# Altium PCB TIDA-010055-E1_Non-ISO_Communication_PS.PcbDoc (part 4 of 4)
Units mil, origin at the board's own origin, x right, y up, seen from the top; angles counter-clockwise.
Board outline 3937.01 x 3346.46 mil, 2 copper layers (Top Layer, Bottom Layer), stack 62 mil thick; 328 components, 142 nets, 761 pads, 214 vias.
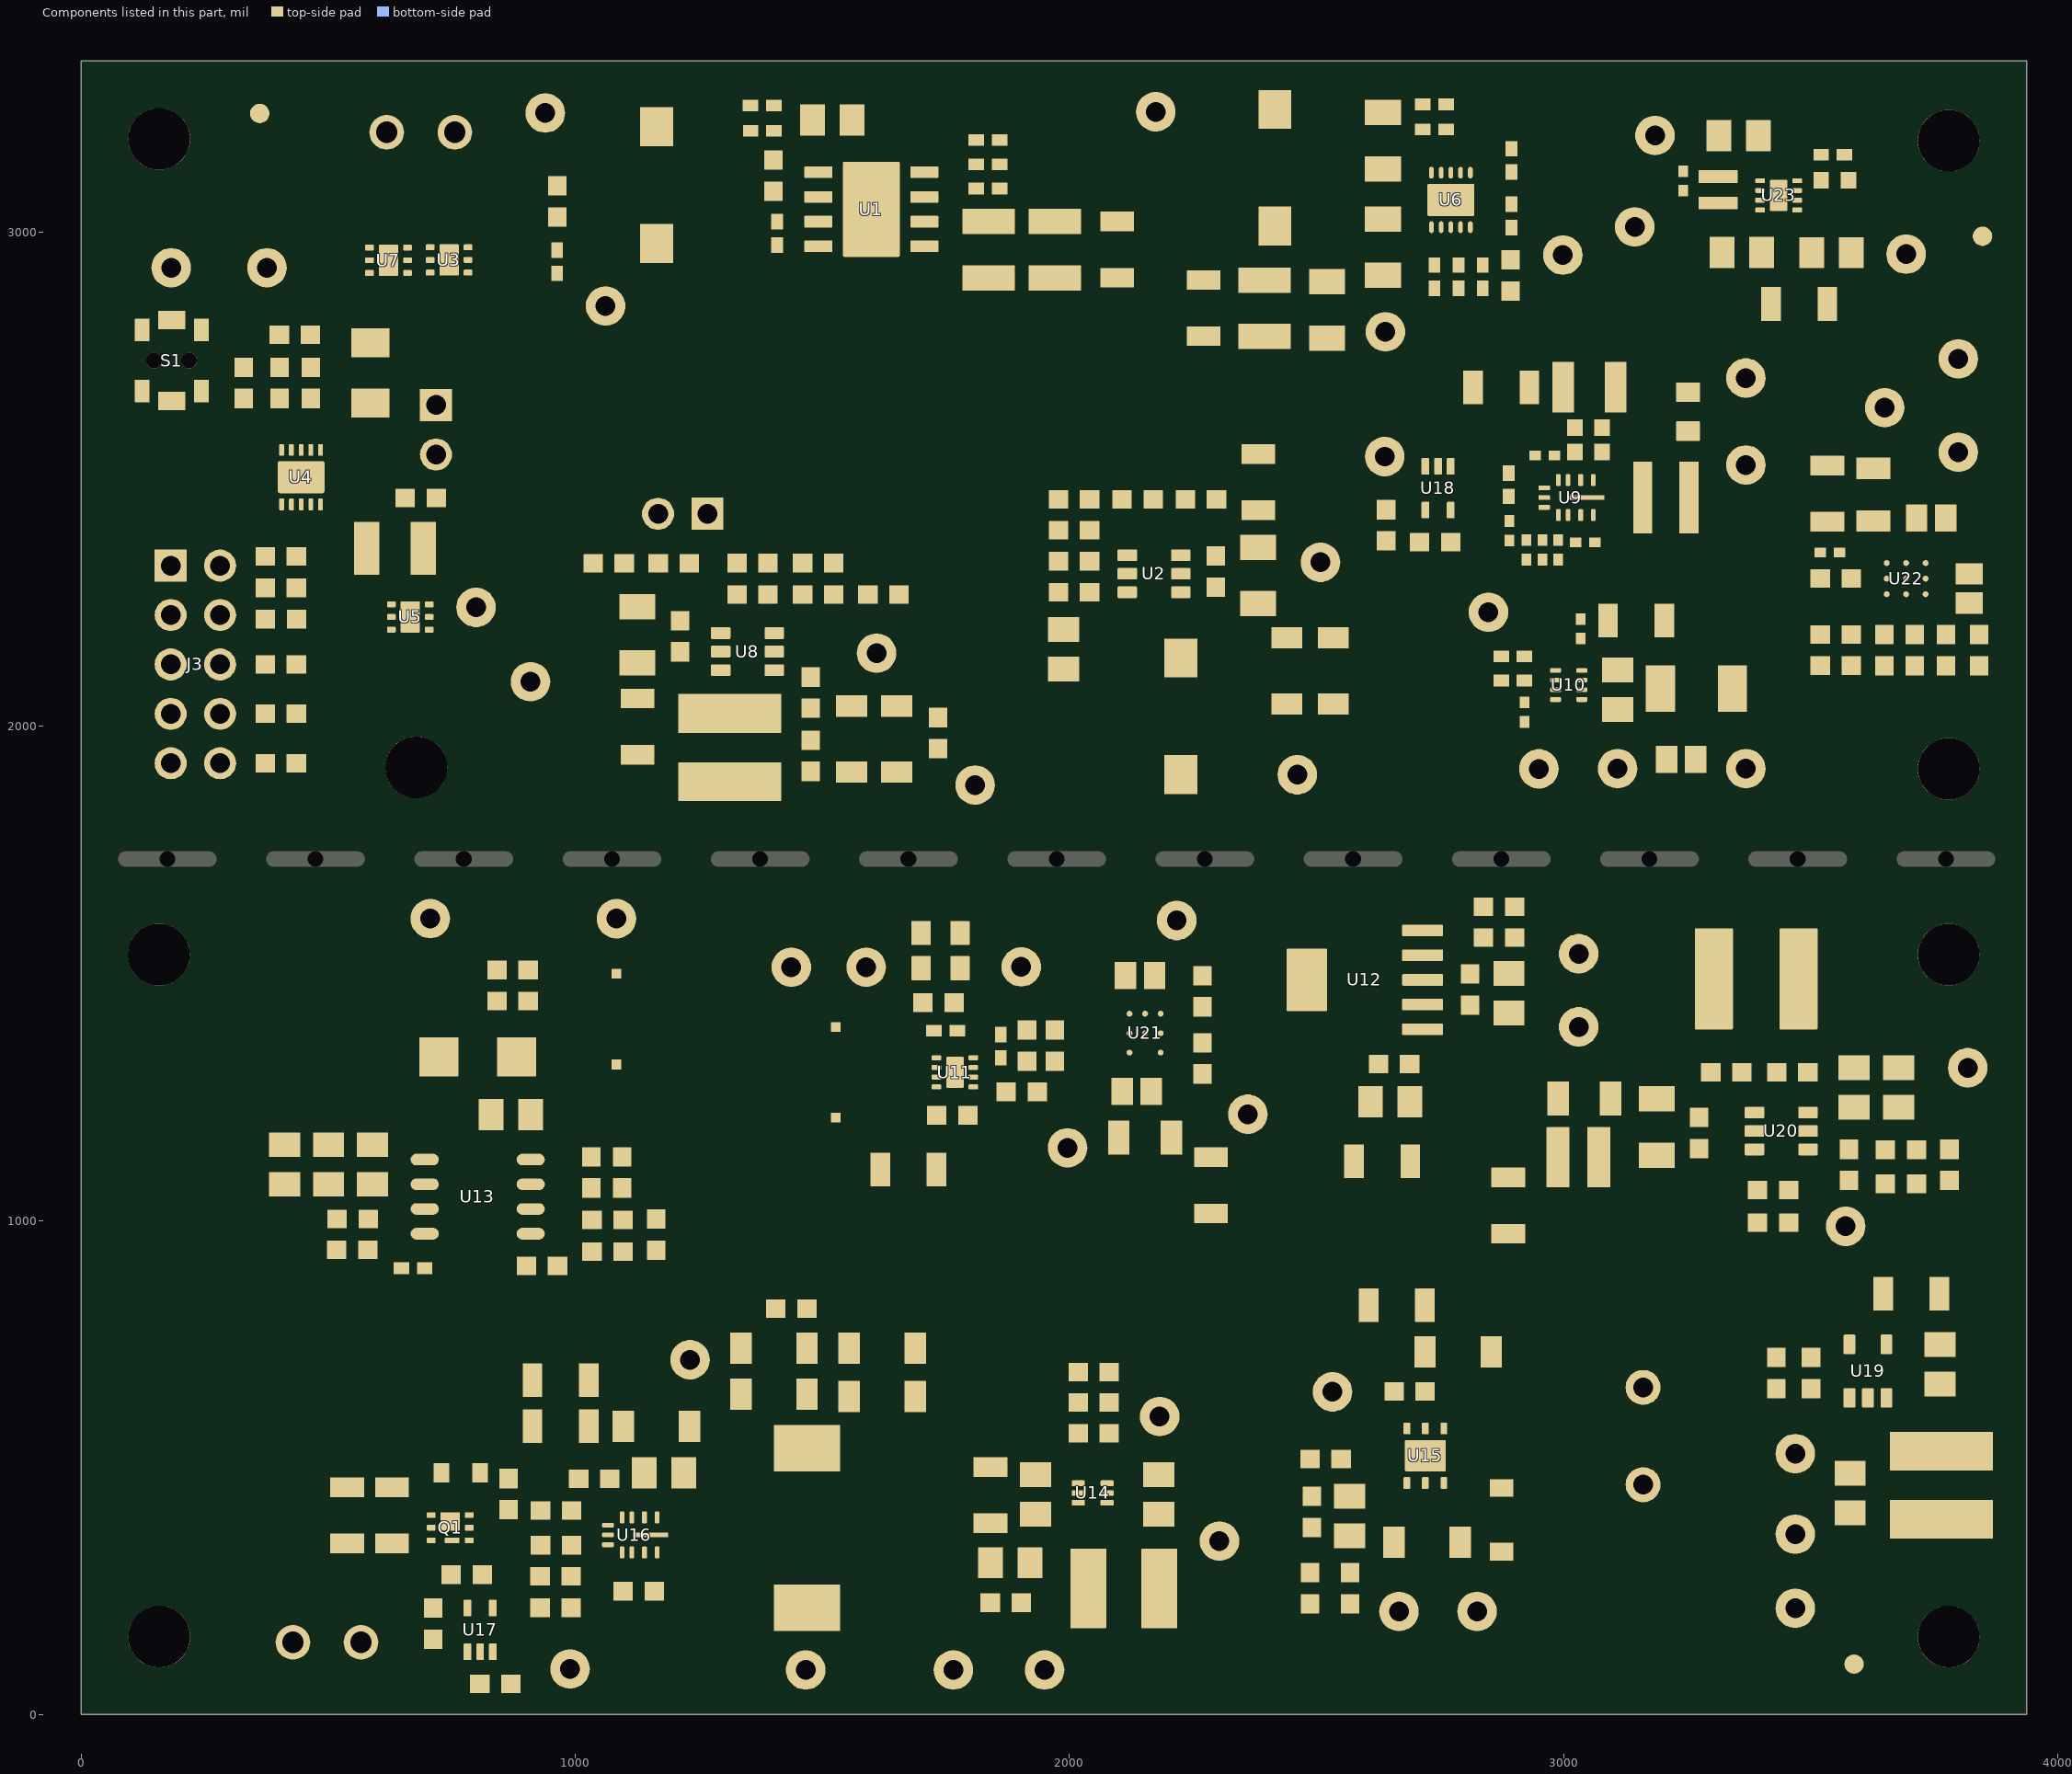
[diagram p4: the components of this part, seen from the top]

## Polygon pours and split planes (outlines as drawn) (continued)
GND_P on Top Layer "net" (solid, remove dead copper, pour order 20): 629.78,2751.18 629.78,2807.35 614.78,2822.35 588.78,2848.35 588.78,2900.35 588.78,3094.18 655.78,3161.18 655.78,3232.62 645,3243.4 487,3243.4 480.78,3237.18 480.78,2860.35 505.78,2835.35 533,2808.13 533,2749.4 539.05,2743.35 554.78,2743.35 621.95,2743.35
NetU3_1 on Top Layer "gn" (solid, remove dead copper, pour order 62): 602,2941.4 602,2978.4 614,2990.4 751,2990.4 764,2977.4 764,2915.4 755,2906.4 612,2906.4 602,2916.4
GND_P on Top Layer "gn" (solid, remove dead copper, pour order 64): 649,2269.4 657.62,2278.02 657.62,2278.19 657.62,2413.19 661.78,2417.35 839.05,2417.35 857,2399.4 857,2181.4 850,2174.4 656,2174.4 649,2181.4
NetC30_2 on Top Layer "gn" (solid, remove dead copper, pour order 66): 3040,2572.1 3040,2741 3030,2751 2912,2751 2902,2741 2902,2585 2909.9,2577.1 2996.96,2577.1 3002.96,2571.1 3002.96,2540.68 3009,2534.63 3037.54,2534.63 3040,2537.1
GND_P on Top Layer "gn" (solid, remove dead copper, pour order 72): 3054,2506.1 3054,2530.1 3060,2536.1 3060,2733.45 3073.65,2747.1 3415,2747.1 3425,2737.1 3425,2658.1 3417,2650.1 3276,2650.1 3193,2650.1 3185,2642.1 3185,2578.1 3179,2572.1 3118,2572.1 3106,2572.1 3101,2567.1 3101,2491.1 3095,2485.1 3057,2485.1 3054,2488.1
NetC33_2 on Top Layer "gn" (solid, remove dead copper, pour order 74): 3187,2544.1 3187,2390.1 3181,2384.1 3131,2384.1 3124,2391.1 3124,2445.1 3116,2453.1 3114,2455.1 3010,2455.1 3006,2459.1 3006,2462.1 3006,2467.88 3009.11,2470.99 3114.24,2470.99 3122.35,2479.1 3122.35,2538.1 3132,2547.74 3183.06,2547.74 3187,2543.81
GND_P on Top Layer "gn" (solid, remove dead copper, pour order 76): 3220.37,1984.83 3159.37,1984.83 3149.37,1994.83 3149.37,2054.83 3142.37,2061.83 3027.37,2061.83 3024.37,2058.83 3024.37,1870.04 3036,1858.4 3218,1858.4 3225,1865.4 3225,1980.2
NetC5_2 on Top Layer "gn" (solid, pour order 92): 1681.13,3003.88 1765.13,3003.88 1777.13,2991.88 2136.13,2991.88 2141.13,2996.88 2141.13,3049.88 2138.13,3052.88 2021.13,3052.88 1681.13,3052.88 1675.13,3046.88 1675.13,3006.88 1678.13,3003.88
NetC8_1 on Top Layer "gn" (solid, pour order 94): 2430,2337.3 2416,2323.3 2276,2323.3 2267,2332.3 2200,2332.3 2195,2337.3 2195,2394.3 2205,2404.3 2333,2404.3 2339,2410.3 2339,2471.3 2345,2477.3 2420,2477.3 2430,2467.3
NetC15_1 on Top Layer "gn" (solid, pour order 104): 2664.68,2942.85 2233.68,2942.85 2228.68,2937.85 2228.68,2878.85 2232.68,2874.85 2233.68,2873.85 2663.68,2873.85 2670.68,2873.85 2681.68,2884.85 2681.68,2935.85 2674.68,2942.85
NetC21_1 on Top Layer "gn" (solid, pour order 110): 1280.73,2166.51 1083.73,2166.51 1073.73,2156.51 1073.73,2038.67 1079.89,2032.51 1157.73,2032.51 1165.73,2040.51 1165.73,2083.72 1172.84,2090.83 1210.29,2090.83 1240.75,2121.3 1254.96,2135.51 1290.73,2135.51 1306.64,2135.51 1315.64,2144.51 1315.64,2159.6 1308.73,2166.51
NetC50_1 on Top Layer "gn" (solid, pour order 116): 944.74,1121.79 944.74,1239.79 966.74,1261.79 1186.2,1261.79 1195.74,1271.33 1195.74,1381.79 1186.74,1390.79 886.74,1390.79 843.74,1390.79 833.74,1380.79 833.74,1295.79 874.74,1254.79 874.74,1199.79 874.74,1113.79 881.74,1106.79 939.74,1106.79 944.74,1111.79
NetC40_1 on Top Layer "gn" (solid, pour order 122): 1753.52,1167.23 1753.52,1066.16 1748.66,1061.31 1698.1,1061.31 1694.15,1065.26 1694.15,1217.86 1709.52,1233.23 1709.52,1270.23 1714.52,1275.23 1736.52,1275.23 1741.52,1270.23 1741.52,1245.23 1753.52,1233.23
NetC35_1 on Top Layer "gn" (solid, pour order 128): 3144.52,2112.99 3144.52,2243.99 3139.52,2248.99 3024.52,2248.99 3020.52,2244.99 3020.52,2206.99 3022.52,2204.99 3063.52,2204.99 3067.52,2200.99 3067.52,2096.99 3077.52,2086.99 3140.52,2086.99 3144.52,2090.99
NetL7_1 on Top Layer "gn" (solid, pour order 134): 1630.18,1184.23 1423.18,1184.23 1413.18,1194.23 1413.18,1261.03 1422.85,1270.7 1601.65,1270.7 1619.18,1288.23 1682.39,1288.23 1688.39,1282.23 1688.39,1242.23 1675.39,1229.23
NetC41_1 on Top Layer "gn" (solid, pour order 138): 1742.18,1325.23 1742.18,1397.44 1719.39,1420.23 1719.39,1615.23 1709.39,1625.23 1513.18,1625.23 1500.18,1612.23 1500.18,1434.23 1486.18,1420.23 1419.18,1420.23 1410.18,1411.23 1410.18,1342.42 1422.85,1329.75 1423.32,1329.28 1685.34,1329.28 1685.34,1328.07 1688.18,1325.23
VO3 on Top Layer "gn" (solid, pour order 140): 3246,1977.4 3282,2013.4 3282,2114.4 3295,2127.4 3431,2127.4 3431,1870.4 3426,1865.4 3419,1858.4 3252,1858.4 3246,1864.4
NetC60_1 on Top Layer "gn" (solid, pour order 142): 2003.54,435.96 1794.54,435.96 1791.54,432.96 1790.54,431.96 1790.54,422.96 1790.54,362.96 1794.54,358.96 1975.49,358.96 2027.32,410.79 2032.54,416.01 2032.54,426.96 2032.54,433.96 2030.54,435.96
NetL9_1 on Top Layer "gn" (solid, pour order 144): 1997.54,179.96 1997.54,350.96 2054.54,407.96 2054.54,431.96 2058.54,435.96 2090.54,435.96 2092.54,433.96 2092.54,156.96 2081.54,145.96 2003.54,145.96 1997.54,151.96
3.3V/2A on Top Layer "gn" (solid, pour order 146): 2139.54,175.96 2139.54,428.96 2146.54,435.96 2348.25,435.96 2364.25,419.96 2364.25,164.66 2345.54,145.96 2145.54,145.96 2139.54,151.96
GND on Top Layer "gn" (solid, pour order 148): 2154.54,458.96 2288.54,458.96 2307.54,477.96 2307.54,650.96 2295.54,662.96 2136.54,662.96 2126.54,652.96 2126.54,597.96 2121.54,592.96 2059.54,592.96 2056.54,589.96 2056.54,466.96 2064.54,458.96
NetC62_1 on Top Layer "gn" (solid, pour order 152): 2698.4,643 2698.4,862 2704.4,868 3009,868 3219.14,657.86 3219.13,646.12 3171.73,598.72 3157.28,598.72 2969,787 2836.4,787 2760.4,787 2755.4,782 2755.4,641 2732.4,618 2732.4,572 2726.4,566 2711.4,566 2705.4,572 2705.4,617 2698.4,624 2698.4,637
GND on Top Layer "gn" (solid, pour order 154): 2679.4,556 2745.4,556 2750.4,561 2750.4,604 2763.4,617 2783.4,637 2783.4,745 2783.4,761 2789.4,767 2880.4,767 2886.4,761 2886.4,577 2841.4,532 2801.4,492 2762.4,492 2732.4,492 2728.4,488 2728.4,166 2723.4,161 2718.4,156 2670.4,156 2626.4,156 2618.4,164 2615.4,167 2615.4,229 2615.4,371 2665.4,421 2704.4,460 2704.4,480 2704.4,487 2699.4,492 2535.4,492 2528.4,499 2528.4,549 2535.4,556
NetD3_1 on Top Layer "gn" (solid, pour order 166): 793,369 701,369 696,374 696,417.94 701.34,423.28 798.72,423.28 801,421 801,377
+5V_P on Top Layer "gn" (solid, pour order 180): 2063,1821.3 2494.3,1821.3 2515,1842 2515,1971 2568,2024 2568,2068 2565,2071 2398,2071 2388,2061 2388,2009 2368,1989 2366.3,1987.3 2053,1987.3 2046,1980.3 2046,1838.3 2063,1821.3
GND_P on Top Layer "gn" (solid, pour order 182): 2204.93,2279.69 2204.93,2222.37 2211,2216.3 2362.7,2216.3 2380,2199 2380,2151 2388,2143 2565,2143 2574,2152 2574,2373 2560,2387 2461,2387 2456,2382 2456,2322 2438,2304 2437.7,2304.3 2275,2304.3 2258,2287.3 2207.3,2287.3 2204,2284
NetC66_1 on Top Layer "gn" (solid, pour order 184): 1109,458 1109,537 1103,543 1003,543 997,549 997,718 1002,723 1126,723 1157,723 1164,716 1168,712 1168,513 1168,450.33 1163.29,445.62 1120.38,445.62 1109,457
24V on Top Layer "gn" (solid, pour order 186): 935,723 785,723 776,714 776,552 782,546 935,546 938,549 938,720
NetL12_1 on Top Layer "vo" (solid, pour order 190): 3881,503 3881,606 3875,612 3715,612 3709,618 3709,659 3702,666 3643,666 3643,497 3652,488 3876,488 3881,493
GND on Top Layer "vo" (solid, pour order 192): 3620,663.47 3604.47,663.47 3600,659 3600,604 3593,597 3472,597 3442,567 3426,551 3426,492 3426,478 3439,465 3443,461 3558,461 3613,461 3620,468
NetC77_1 on Top Layer "vo" (solid, pour order 194): 3605,437 3874,437 3882,429 3882,314.53 3872.47,305 3427,305 3414,318 3414,425 3426,437
NetD2_2 on Top Layer "vo" (solid, pour order 196): 2753.4,410 3213,410 3222,419 3222,487 3207,502 3004.81,502 2984.81,482 2749.57,482 2744.4,476.83 2744.4,419 2753.4,410
NetC76_1 on Top Layer "vo" (solid, pour order 198): 3642,726.47 3804.47,726.47 3810,732 3810,887 3804,893 3739,893 3735,889 3735,796 3722,783 3644,783 3637,776 3637,729.47 3640,726.47
NetC79_1 on Top Layer "vo" (solid, pour order 202): 3413.05,1120.94 3355.94,1120.94 3325,1090 3291,1056 3174,1056 3049,1056 3042,1063 3042,1186 3047,1191 3111,1191 3138,1164 3410,1164 3415,1159 3415,1122.9 3413.05,1120.94
NetC82_1 on Top Layer "vo" (solid, pour order 206): 3722,1277 3554,1277 3547,1284 3547,1357 3540,1364 3438,1364 3429,1373 3429,1602 3440,1613 3613,1613 3642,1584 3642,1415 3677,1380 3884,1380 3901,1363 3901,1141 3882,1122 3758,1122 3753,1127 3753,1267 3743,1277
NetC78_2 on Top Layer "vo" (solid, pour order 208): 3230,1304 3230,1597 3242,1609 3246.02,1613.02 3337.98,1613.02 3350,1601 3350,1378 3327,1355 3327,1275 3318,1266 3261,1266 3230,1297
DC_I on Top Layer "vo" (solid, pour order 210): 474,2407 477.57,2410.57 477.57,2461.72 571.68,2461.72 604.78,2428.62 604.78,2298.1 634.28,2268.59 634.28,2167.28 663.16,2138.4 863.4,2138.4 879,2154 879,2616 991.4,2728.4 2040,2728.4 2058,2746.4 2058,2935.4 2065,2942.4 2147,2942.4 2154,2935.4 2154,2844.4 2171,2827.4 2300.72,2827.4 2311,2817.12 2311,2737 2320,2728 2832,2728 2840,2720 2840,2614 2830.4,2604.4 2688.4,2604.4 2466.4,2604.4 2450,2588 2450,2528 2444,2522 2346,2522 2338,2530 2338,2592.8 2326.4,2604.4 1069.56,2604.4 992,2526.84 992,2041.4 1051,1982.4 1170,1982.4 1172,1980.4 1172,1894.4 1170,1892.4 957.6,1892.4 817.6,2032.4 532,2032.4 514.78,2049.62 514.78,2366.22
NetC91_1 on Top Layer "n" (solid, pour order 238): 3373,2822 3380,2815 3452,2815 3455,2818 3455,2905.42 3468.31,2918.72 3530.72,2918.72 3533,2921 3533,3040.44 3520.37,3053.07 3465.07,3053.07 3461,3049 3461,3032.45 3458,3029.45 3415.94,3029.45 3412,3033.39 3412,3048 3407,3053 3377,3053 3373,3049
VO1 on Top Layer "n" (solid, pour order 240): 3219,2378.45 3219,2621.47 3222.52,2624.99 3463.99,2624.99 3483,2644 3483,2886 3489,2892 3554,2892 3558,2888 3558,2559 3569.61,2547.39 3569.61,2495.61 3562,2488 3446,2488 3438,2480 3438,2184 3425,2171 3182.38,2171 3175,2178.38 3175,2255 3181,2261 3305,2261 3317,2273 3317,2543.34 3312.95,2547.39 3291.29,2547.39 3287.71,2543.81 3287.71,2372.17 3284.52,2368.99 3226.52,2368.99 3218.52,2376.99
NetC93_1 on Top Layer "n" (solid, pour order 242): 3274,3099 3264,3109 3139,3109 3132,3116 3132,3244 3140,3252 3334,3252 3343,3243 3343,3149 3348,3144 3405,3144 3409,3140 3409,3103 3405,3099
GND_P on Top Layer "n" (solid, pour order 244): 3414,3161 3423,3152 3423,3113 3415,3105 3415,3045 3419,3041 3451,3041 3453,3043 3453,3055 3459,3061 3545,3061 3552,3054 3552,2921 3557,2916 3735,2916 3739,2920 3739,3042 3655.33,3125.67 3559.67,3125.67 3555,3121 3555,3082 3551,3078 3495,3078 3483,3090 3458,3090 3455,3093 3455,3121 3474,3140 3474,3244 3466,3252 3368,3252 3362,3246 3362,3166 3367,3161
GND on Bottom Layer "gn" (solid, pour order 174): 341.14,1666.14 57.14,1666.14 36,1645 36,60 60,36 3839.32,36 3937.01,133.69 3937.01,1576.99 3847.86,1666.14
NetL3_1 on Bottom Layer "net" (solid, remove dead copper, pour order 40): 2325.5,3048.62 2577.68,3048.62 2595.86,3030.45 2712.68,3030.45 2720.5,3022.63 2720.5,2972.62 2720.5,2967.26 2712.45,2959.21 2319.91,2959.21 2316.5,2962.62 2316.5,2985.62 2316.5,3039.62
GND_P on Bottom Layer "gn" (solid, remove dead copper, pour order 130): 0,1860 0,3202.4 144.06,3346.46 3798.54,3346.46 3937.01,3207.99 3937.01,1949.01 3772,1784 76,1784
24V on Bottom Layer "gn" (solid, pour order 2): 499,92 499,499 723,723 868,723 879,712 879,560 865,546 787,546 759,518 669,428 669,370 669,90 664,85 506,85
NetC78_2 on Bottom Layer "vo" (solid, pour order 0): 3374,1166 3241,1166 3228,1179 3228,1354 3238,1364 3318,1364 3327,1355 3327,1266.91 3384.03,1209.88 3384.03,1172.03 3378,1166

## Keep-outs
Keep-Out Layer:
  the board outline again, w10
  text ".Layer_Name" at 211.39,-1758.67 h60

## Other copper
Top Layer:
  pour cut-out: 535.74,965.79 544.93,956.6 544.93,906.61 614.3,906.61 614.3,956.34 623.74,965.79
  text ".Layer_Name" at 211.39,-1758.67 h60
Bottom Layer:
  text ".Layer_Name" at 211.39,-1758.67 h60

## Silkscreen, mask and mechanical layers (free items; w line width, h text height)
Top Overlay:
  lines w6: 335.04,2596.35 374.06,2635.37 ; 491.59,2755.33 496.76,2755.33 507.78,2766.35 507.78,2831.35 ; 843,294 852,294 856,298 856,304 ; 901.02,385.34 886.2,370.52 886.2,176.2 904.4,158 1029,158 1074,113 1074,11 1211,11 1218,18 1218,207 1031.8,207 1031.8,439.8 1020.98,439.8 ; 901.02,439.8 901.02,450.02 901.2,450.2 978.02,450.2 ; 948,715 990,715 ; 964,170 964,186 ; 1096,44 1096,155 ; 1097.41,2380.23 1108.41,2369.23 1127.51,2369.23 1139.22,2357.52 ; 1337,3133.4 1337,3184.05 ; 1360.41,2388.23 1360.41,2367.23 ; 1489.41,2387.23 1489.41,2366.23 ; 1802.54,426.96 1802.54,459.96 ; 1877.54,426.96 1877.54,459.96 ; 1879.54,547.96 1879.54,530.66 1891.01,519.19 ; 2647.4,791 2680.4,791 ; 2647.4,866 2680.4,866 ; 3023,1933 3023,1953.47 3051.94,1982.4 3069.37,1999.83 ; 3102.52,2587.99 3166.52,2587.99 ; 3128,2306.1 3087,2306.1 ; 3500,966 3500,1014 3545,1059 ; 3678,2043 3683.73,2048.73 3683.73,2062.27 3683.73,2094.02 ; 3690,1018 3690,1038 ; 964,186 959,181 971,181 966,186 964,186 ; 1096,155 1086,145 1105,145 1096,154 1096,155 ; 1360.41,2367.23 1362.41,2367.23 1368.41,2373.23 1354.41,2373.23 1360.41,2367.23 ; 1489.41,2366.23 1490.41,2366.23 1496.41,2372.23 1483.41,2372.23 1489.41,2366.23 ; 3087,2306.1 3087,2305.1 3094,2298.1 3094,2313.1 3087,2306.1 ; 3690,1038 3684,1032 3697,1032 3691,1038 3690,1038 ; 2907,2311 2907,2391.1 2916,2400.1 3077,2400.1 3115,2362.1 3349,2362.1 3349,2263.1 2954.9,2263.1 2907,2311
  lines w10: 0.58,1731.42 3936,1731.42
  text "VOUT_DCDC_3.3V" at 2014,3312 h30
  text "VCC_P_3.3V" at 869,3302.4 h30
  text "GND" at 918,2787.4 h30
  text "GND" at 2905,2757 h30 r90
  text "GND" at 3599,2751 h30
  text "LOAD" at 3898,2689 h30 r90
  text "GND" at 3465,2664 h30 r90
  text "'.PRJ_Number'" at 891,2648.42 h40
  text "VO1_5V" at 3460,2440 h30 r90
  text "VO4_3.3V" at 3899,2438 h30 r90
  text "GND" at 2479,2393 h30
  text "GND" at 868,2253.4 h30
  text "EN" at 2786,2201 h30 r90
  text "GND" at 1669,2160 h30
  text "DC_I" at 866,1993.4 h30
  text "VO3_1.5V" at 3474,1808 h30 r90
  text "+5V_P" at 2395,1798 h30
  text "5V_S" at 1766,1789 h30
  text "GND" at 3114,1786 h30
  text "VO2_3.3V" at 1149,1630 h30
  text "1.5V" at 2286,1622 h30
  text "1.2V" at 1543,1619 h30
  text "GND" at 776,1600 h30
  text "GND" at 1964,1541 h30
  text "2.5V" at 3123,1490 h30 r90
  text "GND" at 3123,1353 h30 r90
  text "+3.3V" at 3914,1236 h30 r90
  text "GND" at 1968,1016 h30
  text "GND" at 2147,704 h30
  text "GND" at 1087,701 h30
  text "GND" at 3528,538 h30
  text "+3.3VSEC" at 3512,296 h30
  text "3.3V/2A" at 2397,247 h30 r90
  text "GND" at 2626,80 h30
  text "24V" at 2781,79 h30
  text ".Layer_Name" at 211.39,-1758.67 h60
Bottom Overlay:
  text ".Layer_Name" at 211.39,-1758.67 h60
Top Paste:
  text ".Layer_Name" at 211.39,-1758.67 h60
Bottom Paste:
  text ".Layer_Name" at 211.39,-1758.67 h60
Top Solder:
  text ".Layer_Name" at 211.39,-1758.67 h60
  text ".Layer_Name" at 211.39,-1758.67 h60
Bottom Solder:
  text ".Layer_Name" at 211.39,-1758.67 h60
Drill Guide:
  text ".Layer_Name" at 211.39,-1758.67 h60
M1 Board Outline:
  the board outline again, w10
M2 Board Dimensions:
  rectangle: -365.61,-1175.18 -240.61,-1050.18
  rectangle: -240.61,-1300.18 134.39,-1175.18
  lines w7: -365.61,-1175.18 634.39,-1175.18 ; -240.61,-1300.18 -240.61,-1050.18 ; -115.61,-1300.18 -115.61,-1050.18 ; 134.39,-1300.18 134.39,-1050.18 ; 384.39,-1300.18 384.39,-1050.18 ; -365.61,-1300.18 634.39,-1300.18 634.39,-1050.18 -365.61,-1050.18 -365.61,-1300.18
M3 3D STEP Top:
  text ".Layer_Name" at 211.39,-1758.67 h60
M4 3D STEP Bottom:
  text ".Layer_Name" at 211.39,-1758.67 h60
M5 Assembly Top:
  circle w6: c1311,2022 r14.21
  circle w6: c782,113 r5
  circle w6: c2772,2538 r5.1
  circle w6: c2645,1387 r6.32
  circle w10: c3583,617 r9.06
  lines w10: -657.61,-1830.35 5942.39,-1830.35 ; -657.61,-1627.01 5944.39,-1627.01 ; -657.61,-1423.68 -657.61,-2033.68 3347.39,-2033.68 5944.39,-2033.68 5944.39,-1423.68 -657.11,-1423.68 -657.11,-2033.68 918.39,-2033.68 ; 1807.39,-2033.68 1807.39,-1423.68 ; 3074.39,-1627.01 3074.39,-1423.68 ; 3914.39,-1627.01 3914.39,-1423.68 ; 4536.39,-2040.18 4536.39,-1837.35
  text "COMPONENTS MARKED 'DNP' SHOULD NOT BE POPULATED." at 787.89,-1218.68 h25
  text "ASSEMBLY VARIANT:" at 787.39,-1334.18 h25
  text ".VariantName" at 1823.39,-1334.18 h25
  text "PCB VIEWED FROM TOP SIDE" at -594.11,-1555.85 h25
  text "BOARD #:" at 1882.39,-1555.85 h25
  text "REV:" at 3272.39,-1555.85 h25
  text ".PCB_Rev" at 3563.89,-1555.85 h25
  text "SVN REV:" at 4110.39,-1555.85 h25
  text ".VersionControl_RevNumber" at 4616.39,-1555.85 h25
  text ".PRJ_Number" at 2186,-1563.6 h25
  text "'.Layer_Name'" at 177,-1756.6 h25
  text "TID #:" at 1882.39,-1759.18 h25
  text ".TID" at 2427.89,-1759.18 h25
  text "LAYER NAME =" at -588.11,-1761.67 h25
  text "PLOT NAME =" at -594.11,-1964.52 h25
  text ".plot_File_Name" at 211.39,-1964.52 h25
  text "GENERATED    :" at 1884.39,-1964.52 h25
  text ".Print_Date" at 2753.89,-1964.52 h25
  text ".Print_Time" at 3482.89,-1964.52 h25
  text "TEXAS INSTRUMENTS" at 4747.39,-1964.52 h25
M6 Assembly Bottom:
  lines w10: -658.11,-1627.51 5943.89,-1627.51 ; -656.11,-1830.85 5943.89,-1830.85 ; 749.89,-2040.68 749.89,-1837.85 ; 1371.89,-1627.51 1371.89,-1424.18 ; 2211.89,-1627.51 2211.89,-1424.18 ; 3478.89,-2034.18 3478.89,-1424.18 ; 4367.89,-2034.18 5943.39,-2034.18 5943.39,-1424.18 -658.11,-1424.18 -658.11,-2034.18 1938.89,-2034.18 5943.89,-2034.18 5943.89,-1424.18
  text "COMPONENTS MARKED 'DNP' SHOULD NOT BE POPULATED." at 5736.39,-1218.18 h25
  text ".VariantName" at 4692.39,-1334.18 h25
  text "ASSEMBLY VARIANT:" at 5731.39,-1334.18 h25
  text ".VersionControl_RevNumber" at 669.89,-1556.35 h25
  text "SVN REV:" at 1175.89,-1556.35 h25
  text ".PCB_Rev" at 1722.39,-1556.35 h25
  text "REV:" at 2013.89,-1556.35 h25
  text ".PRJ_Number" at 2858.39,-1556.35 h25
  text "BOARD #:" at 3403.89,-1556.35 h25
  text "PCB VIEWED FROM BOTTOM SIDE" at 5880.39,-1556.35 h25
  text "'.Layer_Name'" at 4987,-1749.6 h25
  text ".TID" at 2858.39,-1759.68 h25
  text "TID #:" at 3403.89,-1759.68 h25
  text "LAYER NAME =" at 5846,-1760.6 h25
  text "TEXAS INSTRUMENTS" at 538.89,-1965.02 h25
  text ".Print_Time" at 1803.39,-1965.02 h25
  text ".Print_Date" at 2532.39,-1965.02 h25
  text "GENERATED    :" at 3401.89,-1965.02 h25
  text ".plot_File_Name" at 5074.89,-1965.02 h25
  text "PLOT NAME =" at 5880.39,-1965.02 h25
M9 Title Sheet:
  drawing of 57 lines, arcs and shapes, not listed
  text "1" at 374.22,7136.32 h70
  text "2" at 2869.89,7136.32 h70
  text "3" at 5359.23,7136.32 h70
  text "4" at 7865.9,7136.32 h70
  text "5" at 10364.89,7136.32 h70
  text "6" at 12869.89,7136.32 h70
  text "A" at -782.11,5993.32 h70
  text "A" at 14017.89,5993.32 h70
  text "A" at 14019.91,5992.54 h70
  text "B" at -782.11,3613.32 h70
  text "B" at 14017.89,3613.32 h70
  text "B" at 14019.91,3612.54 h70
  text "C" at -782.11,1238.32 h70
  text "C" at 14017.89,1238.32 h70
  text "C" at 14019.91,1237.54 h70
  text "PROJECT TITLE:" at 10977.89,-622.68 h45
  text ".PRJ_Title" at 11027.89,-756.01 h70
  text "DESIGNED FOR:" at 10977.89,-923.68 h45
  text ".PRJ_Customer" at 11027.89,-1063.68 h70
  text "D" at -782.11,-1131.68 h70
  text "D" at 14017.89,-1131.68 h70
  text "FILE NAME:" at 10977.89,-1223.68 h45
  text ".PCB_File_Name_No_Path" at 11027.89,-1343.68 h70
  text "Texas Instruments (TI) and/or its licensors do not warrant the accuracy or completeness of this specification" at 6008.39,-1505.52 h45
  text "ENGINEER:" at 10977.89,-1513.68 h45
  text "LAYOUT BY:" at 12482.89,-1513.68 h45
  text "or any information contained therein. TI and/or its licensors do not warrant that this design will meet" at 5963.4,-1618.18 h45
  text ".PRJ_Engineer" at 11027.89,-1668.67 h70
  text ".PCB_Layout" at 12533.39,-1668.67 h70
  text "the specifications, will be suitable for your application or fit for any particular purpose, or will operate in" at 5963.4,-1730.85 h45
  text "ALTIUM DESIGNER VERSION:" at 12482.89,-1823.68 h45
  text "an implementation. TI and/or its licensors do not warrant that the design is production worthy. You should" at 5963.4,-1843.52 h45
  text "completely validate and test your design implementation to confirm the system functionality for your application." at 6008.39,-1956.18 h45
  text ".print_Scale" at 11027.89,-1957.01 h70
  text ".Application_BuildNumber" at 12533.39,-1957.01 h70
  text "1" at 374.22,-2163.68 h70
  text "2" at 2869.89,-2163.68 h70
  text "3" at 5359.23,-2163.68 h70
  text "4" at 7865.9,-2163.68 h70
  text "5" at 10364.89,-2163.68 h70
  text "6" at 12869.89,-2163.68 h70
M10 Fab Notes:
  drawing of 227 lines, arcs and shapes, not listed
  text "DESIGN INFORMATION" at 12005.86,5899.76 h60
  text "(REFER ALSO ARRAY/PANEL PROFILING INFORMATION)" at 11654.35,5733.69 h60
  text "BOARD SIZE" at 10968.35,5729.4 h60
  text "85MM" at 12227,5605.4 h60
  text "100MM" at 11448,5602.4 h60
  text "X" at 11936.35,5601.58 h60
  text "Number of Layers :" at 11371.34,5404.4 h60
  text "2" at 12443.89,5399.4 h60
  text "8" at 12444.82,5267.61 h60
  text "MIN. TRACK WIDTH:" at 11371.34,5265.4 h60
  text "MIL" at 12622.34,5265.4 h60
  text "7.874" at 12319,5139.4 h60
  text "MIN. CLEARANCE:" at 11371.34,5133.4 h60
  text "MIL" at 12622.34,5133.4 h60
  text "MIN. VIA DRILL SIZE:" at 11371.34,5001.4 h60
  text "7.874" at 12309.82,5001.61 h60
  text "MIL" at 12622.34,5001.4 h60
  text "5.90 MIL" at 12066.35,4859.69 h60
  text "MINIMUM ANNULAR RING" at 11042.11,4855.41 h60
  text "EXTERNAL" at 12957.89,4844.4 h60
  text "PER" at 11242.11,4737.41 h60
  text "IPC-D-275 CLASS 2 LEVEL C" at 11462.11,4737.4 h60
  text "+/-" at 12557.89,4624.4 h60
  text "MIL, HOLES" at 12950.34,4625.11 h60
  text "+/-" at 13411.89,4624.4 h60
  text "REGISTRATION TOLERANCES:" at 11042.11,4619.4 h60
  text "METAL" at 12241.89,4619.4 h60
  text "5" at 12818.09,4619.41 h60
  text "3" at 13651.09,4619.41 h60
  text "MIL" at 13767.34,4619.4 h60
  text "MATERIAL:" at 10967.35,4409.94 h60
  text "FR-4 High Tg" at 11953.79,4269.61 h60
  text "X" at 11794.89,4261.4 h60
  text "FR-408" at 11388.35,4261.04 h60
  text "OTHER" at 12876.35,4261.04 h60
  text "63 MIL (1.6mm) +/-10%" at 11708.45,4098.32 h60
  text "THICKNESS:" at 11042.11,4094.04 h60
  text "X" at 11580.28,4094.04 h60
  text "OTHER" at 12993.35,4094.04 h60
  text "TOLERANCE:" at 11042.11,3936.04 h60
  text "X" at 11881.42,3936.04 h60
  text "ANSI IPC-6012 TYPE 3 CLASS 2" at 12068.36,3936.04 h60
  text "OTHER +/-" at 12068.35,3780.04 h60
  text "BOW & TWIST:" at 11042.11,3623.04 h60
  text "X" at 11881.42,3623.04 h60
  text "ANSI IPC-6012 TYPE 3 CLASS 2" at 12068.36,3623.04 h60
  text "OTHER +/-" at 12068.35,3464.53 h60
  text "COPPER THICKNESS (FINISHED):" at 10967.35,3329.04 h60
  text "1.4MIL (1oz)" at 11847.34,3176.32 h60
  text "2MIL (1.4oz)" at 12614.35,3176.32 h60
  text "2.8MIL (2oz)" at 13341.35,3176.32 h60
  text "OUTER:" at 11324.35,3172.04 h60
  text "X" at 11718.89,3171.4 h60
  text "1.4MIL (1oz)" at 11847.34,3019.32 h60
  text "2.8MIL (2oz)" at 12614.35,3019.32 h60
  text "N/A" at 13340.89,3019.69 h60
  text "INNER SIGNAL:" at 11035.26,3015.04 h60
  text "X" at 13211.37,3008.04 h60
  text "DRILLING:" at 10967.35,2876.04 h60
  text "REFERENCE:" at 11042.11,2759.04 h60
  text "X" at 11690.35,2759.04 h60
  text "AS SHOWN" at 11877.34,2759.04 h60
  text "X" at 12591.35,2759.04 h60
  text "NC_DRILL FILES" at 12728.34,2759.04 h60
  text "PTH MIN COPPER THICKNESS:" at 11042.11,2601.04 h60
  text "X" at 12392.35,2601.04 h60
  text "1MIL" at 12529.34,2601.04 h60
  text "OTHER" at 13026.35,2601.04 h60
  text "BOARD FINISH:" at 10967.35,2442.04 h60
  text "SILKSCREEN:" at 11122.57,2324.04 h60
  text "X" at 12071.35,2324.04 h60
  text "TOP" at 12197.34,2324.04 h60
  text "X" at 12581.35,2324.04 h60
  text "BOTTOM" at 12708.34,2324.04 h60
  text "SILKSCREEN COLOR:" at 11122.57,2157.04 h60
  text "X" at 12070.3,2157.04 h60
  text "WHITE" at 12197.34,2157.04 h60
  text "OTHER" at 12708.34,2157.04 h60
  text "SOLDER RESIST COLOR:" at 11122.57,1987.04 h60
  text "X" at 11690.31,1827.84 h60
  text "GREEN" at 11817.34,1827.84 h60
  text "BLUE" at 12408.34,1827.84 h60
  text "OTHER" at 12946.35,1827.84 h60
  text "IMMERSION GOLD (ENIG)" at 12028.34,1639.32 h60
  text "ENEPIG" at 13365.89,1636.04 h60
  text "SURFACE FINISH:" at 10967.35,1635.04 h60
  text "X" at 11841.4,1635.04 h60
  text "IMM. TIN/SILVER OR EQUIV" at 11296.89,1478.04 h60
  text "OTHER" at 12728.35,1478.04 h60
  text "ARRAY/PANEL:" at 10967.35,1299.04 h60
  text "CUT AND TRIM PER MECH LAYER 1" at 12028.35,1294.76 h60
  text "N.C. ROUTE" at 12028.34,1143.04 h60
  text "X" at 12707.35,1143.04 h60
  text "V. SCORE" at 12894.35,1143.04 h60
  text "CERTIFICATION:" at 10967.35,1006.04 h60
  text "MATERIALS AND WORKMANSHIP FOR ALL PCBS" at 11692.35,1006.04 h60
  text "TO MEET OR EXCEED THE REQUIREMENTS OF:" at 11692.35,908.04 h60
  text "X" at 11318.85,771.54 h60
  text "ANSI IPC-A-600F CLASS ->" at 11457.85,771.54 h60
  text "X" at 13096.9,771.54 h60
  text "2" at 13215.85,771.54 h60
  text "1" at 12900.85,770.04 h60
  text "3" at 13569.85,770.04 h60
  text "X" at 11320.9,612.04 h60
  text "UL 94V-0" at 11457.85,612.04 h60
  text "X" at 12132.9,612.04 h60
  text "RoHS" at 12269.85,612.04 h60
  text "OTHER" at 12914.25,612.04 h60
  text "PER ORDER" at 13311.31,612.04 h60
  text "X" at 13261,482.4 h60
  text "VIA TENTING:" at 12184.89,478.4 h60
  text "ADDITIONAL REQUIREMENTS:" at 10967.35,471.04 h60
  text "YES" at 12734.55,469.32 h60
  text "NO" at 13099.36,464.09 h60
  text "MICROSECTION:" at 11042.11,356.04 h60
  text "YES" at 11947.85,356.04 h60
  text "IMPEDANCE CONTROL:" at 12206.89,349.4 h60
  text "YES" at 13190.89,348.4 h60
  text "X" at 13732.89,341.4 h60
  text "NO" at 13566.36,331.09 h60
  text "REQUIRED" at 12809.34,199.9 h60
  text "BARE BOARD ELEC. TEST:" at 11042.11,197.04 h60
  text "NONE" at 12347.85,197.04 h60
  text "X" at 12682.35,197.04 h60
  text "PER ORDER" at 13401.35,197.04 h60
  text "MANUFACTURER'S UL:" at 11042.11,40.04 h60
  text "RAIL" at 12207.85,35.76 h60
  text "METAL" at 12699.66,35.76 h60
  text "X" at 13074.89,35.4 h60
  text "SILK" at 13211.34,35.76 h60
M11 Gerber Information:
  lines w10: -657.61,-1830.35 5942.39,-1830.35 ; -657.61,-1627.01 5944.39,-1627.01 ; -657.61,-1423.68 -657.61,-2033.68 3347.39,-2033.68 5944.39,-2033.68 5944.39,-1423.68 -657.11,-1423.68 -657.11,-2033.68 918.39,-2033.68 ; 1807.39,-2033.68 1807.39,-1423.68 ; 3074.39,-1627.01 3074.39,-1423.68 ; 3914.39,-1627.01 3914.39,-1423.68 ; 4536.39,-2040.18 4536.39,-1837.35
  text "ALL ARTWORK VIEWED FROM TOP SIDE" at -594.11,-1555.85 h60
  text "BOARD #:" at 1882.39,-1555.85 h60
  text ".PRJ_Number" at 2427.89,-1555.85 h60
  text "REV:" at 3272.39,-1555.85 h60
  text ".PCB_Rev" at 3563.89,-1555.85 h60
  text "SVN REV:" at 4110.39,-1555.85 h60
  text ".VersionControl_RevNumber" at 4616.39,-1555.85 h60
  text "LAYER NAME =" at -594.11,-1758.67 h60
  text "TID #:" at 1882.39,-1759.18 h60
  text ".TID" at 2427.89,-1759.18 h60
  text "PLOT NAME =" at -594.11,-1964.52 h60
  text ".plot_File_Name" at 211.39,-1964.52 h60
  text "GENERATED    :" at 1884.39,-1964.52 h60
  text ".Print_Date" at 2753.89,-1964.52 h60
  text ".Print_Time" at 3482.89,-1964.52 h60
  text "TEXAS INSTRUMENTS" at 4747.39,-1964.52 h60
M12 Stackup:
  drawing of 191 lines, arcs and shapes, not listed
  text "Layer" at 5053.58,3224 h60
  text "Name" at 5463.49,3224 h60
  text "Material" at 6393.23,3224 h60
  text "Thickness" at 7253,3224 h60
  text "Constant" at 7902.84,3224 h60
  text "Board Layer Stack" at 8472.7,3224 h60
  text "1" at 5053.58,3104 h60
  text "Top Overlay" at 5463.49,3104 h60
  text "2" at 5053.58,2984 h60
  text "Top Solder" at 5463.49,2984 h60
  text "Solder Resist" at 6393.23,2984 h60
  text "0.40mil" at 7253,2984 h60
  text "3.5" at 7902.84,2984 h60
  text "3" at 5053.58,2864 h60
  text "Top Layer" at 5463.49,2864 h60
  text "Copper" at 6393.23,2864 h60
  text "1.40mil" at 7253,2864 h60
  text "4" at 5053.58,2744 h60
  text "Dielectric1" at 5463.49,2744 h60
  text "FR-4 High Tg" at 6393.23,2744 h60
  text "59.20mil" at 7253,2744 h60
  text "4.8" at 7902.84,2744 h60
  text "5" at 5053.58,2624 h60
  text "Bottom Layer" at 5463.49,2624 h60
  text "Copper" at 6393.23,2624 h60
  text "1.40mil" at 7253,2624 h60
  text "6" at 5053.58,2504 h60
  text "Bottom Solder" at 5463.49,2504 h60
  text "Solder Resist" at 6393.23,2504 h60
  text "0.40mil" at 7253,2504 h60
  text "3.5" at 7902.84,2504 h60
  text "7" at 5053.58,2384 h60
  text "Bottom Overlay" at 5463.49,2384 h60
M13 Component Bodies Top:
  text ".Layer_Name" at 211.39,-1758.67 h60
M14 Component Bodies Bottom:
  text ".Layer_Name" at 211.39,-1758.67 h60
M15 Courtyards Top:
  text ".Layer_Name" at 211.39,-1758.67 h60
M16 Courtyards Bottom:
  text ".Layer_Name" at 211.39,-1758.67 h60
Drill Drawing:
  circle w10: c4213.62,5780.68 r33.33
  lines w10: 4180.29,5447.34 4246.96,5447.34 4246.96,5514.01 4180.29,5514.01 4180.29,5447.34 ; 4180.29,5630.68 4213.62,5597.34 4246.96,5630.68 4213.62,5664.01 4180.29,5630.68 ; 4180.29,5964.01 4246.96,5964.01 4213.62,5897.34 4180.29,5964.01 ; 4180.29,6064.01 4196.96,6064.01 4196.96,6047.34 4230.29,6047.34 4230.29,6064.01 4246.96,6064.01 4246.96,6097.34 4230.29,6097.34 4230.29,6114.01 4196.96,6114.01 4196.96,6097.34 4180.29,6097.34 4180.29,6064.01 ; 4180.29,6197.34 4213.62,6214.01 4246.96,6197.34 4230.29,6230.68 4246.96,6264.01 4213.62,6247.34 4180.29,6264.01 4196.96,6230.68 4180.29,6197.34 ; 4180.29,6364.01 4196.96,6364.01 4213.62,6347.34 4230.29,6364.01 4246.96,6364.01 4230.29,6380.68 4246.96,6397.34 4230.29,6397.34 4213.62,6414.01 4196.96,6397.34 4180.29,6397.34 4196.96,6380.68 4180.29,6364.01 ; 4180.29,6564.01 4246.96,6564.01 4213.62,6497.34 4180.29,6564.01 ; 4193.62,5950.68 4233.62,5950.68 4213.62,5910.68 4193.62,5950.68 ; 4193.62,6070.68 4203.62,6070.68 4203.62,6060.68 4223.62,6060.68 4223.62,6070.68 4233.62,6070.68 4233.62,6090.68 4223.62,6090.68 4223.62,6100.68 4203.62,6100.68 4203.62,6090.68 4193.62,6090.68 4193.62,6070.68
  lines w15: 4120.5,5252.34 7695.56,5252.34 ; 4120.5,6602.34 7695.56,6602.34 ; 4671.38,5102.34 4671.38,6752.34 ; 5271.22,5102.34 5271.22,6752.34 ; 6410.88,5102.34 6410.88,6752.34 ; 6916.76,5102.34 6916.76,6752.34 ; 4120.5,5102.34 7695.56,5102.34 7695.56,6752.34 4120.5,6752.34 4120.5,5102.34
  text "Symbol" at 4210.5,6647.34 h72
  text "Count" at 4716.38,6647.34 h72
  text "Hole Size" at 5316.22,6647.34 h72
  text "Plated" at 6455.88,6647.34 h72
  text "Hole Type" at 6961.76,6647.34 h72
  text "32" at 4716.38,6497.34 h60
  text "7.87mil (0.200mm)" at 5316.22,6497.34 h60
  text "PTH" at 6455.88,6497.34 h60
  text "Round" at 6961.76,6497.34 h60
  text "2" at 4716.38,6347.34 h60
  text "8.00mil (0.203mm)" at 5316.22,6347.34 h60
  text "PTH" at 6455.88,6347.34 h60
  text "Round" at 6961.76,6347.34 h60
  text "179" at 4716.38,6197.34 h60
  text "12.00mil (0.305mm)" at 5316.22,6197.34 h60
  text "PTH" at 6455.88,6197.34 h60
  text "Round" at 6961.76,6197.34 h60
  text "1" at 4716.38,6047.34 h60
  text "16.00mil (0.406mm)" at 5316.22,6047.34 h60
  text "PTH" at 6455.88,6047.34 h60
  text "Round" at 6961.76,6047.34 h60
  text "2" at 4716.38,5897.34 h60
  text "31.50mil (0.800mm)" at 5316.22,5897.34 h60
  text "NPTH" at 6455.88,5897.34 h60
  text "Round" at 6961.76,5897.34 h60
  text "13" at 4716.38,5747.34 h60
  text "32.00mil (0.813mm)" at 5316.22,5747.34 h60
  text "NPTH" at 6455.88,5747.34 h60
  text "Slot" at 6961.76,5747.34 h60
  text "67" at 4716.38,5597.34 h60
  text "40.00mil (1.016mm)" at 5316.22,5597.34 h60
  text "PTH" at 6455.88,5597.34 h60
  text "Round" at 6961.76,5597.34 h60
  text "4" at 4716.38,5447.34 h60
  text "43.31mil (1.100mm)" at 5316.22,5447.34 h60
  text "PTH" at 6455.88,5447.34 h60
  text "Round" at 6961.76,5447.34 h60
  text "8" at 4716.38,5297.34 h60
  text "125.00mil (3.175mm)" at 5316.22,5297.34 h60
  text "NPTH" at 6455.88,5297.34 h60
  text "Round" at 6961.76,5297.34 h60
  text "D" at 4181.41,5287.35 h66.67
  text "308 Total" at 4716.38,5147.34 h60
  text "Slot definitions :" at 4210.5,5002.37 h60
  text "Routed Path Length" at 5243.19,5002.37 h60
  text "= Calculated from tool start centre position to tool end centre position." at 6345.86,5002.37 h60
  text "Hole Length" at 5243.19,4902.4 h60
  text "= Routed Path Length + Tool Size = Slot length as defined in the PCB layout" at 5935.99,4902.4 h60
  text "Drill Table" at 4076.77,4731.4 h60
  text "FOR 7.874MIL DRILL +0/-7.874MIL" at 4077,4595.4 h60
  text "FOR 12MIL DRILL +0/-12MIL" at 4077,4496.4 h60
  text "FOR 16MIL DRILL +0/-16MIL" at 4076.77,4407.4 h60
  text "FOR PTH DRILL +/-3MIL" at 4072.51,4320.85 h60
  text "FOR NPTH DRILL +/-2MIL" at 4076.77,4237.4 h60
  text ".Layer_Name" at 211.39,-1758.67 h60
Mechanical 17:
  text ".Layer_Name" at 211.39,-1758.67 h60
Mechanical 18:
  text ".Layer_Name" at 211.39,-1758.67 h60
Mechanical 19:
  text ".Layer_Name" at 211.39,-1758.67 h60

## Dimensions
0,0 to 3937.01,0 on M2 Board Dimensions
0,0 to 0,3346.46 on M2 Board Dimensions
-365.61,-1300.18 to 634.39,-1300.18 on M2 Board Dimensions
